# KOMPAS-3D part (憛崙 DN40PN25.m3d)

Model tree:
1. Объединить компоненты:1  (labels: СЕНС DN40PN25)

Referenced files in D:\Савин\!СЕНСОР\3D для заказчика\!Новый перечень\СЕНС\1. СЕНС\DN40\: СЕНС DN40PN25.a3d
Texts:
  СЕНС DN40PN25
  ООО НПП Сенсор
